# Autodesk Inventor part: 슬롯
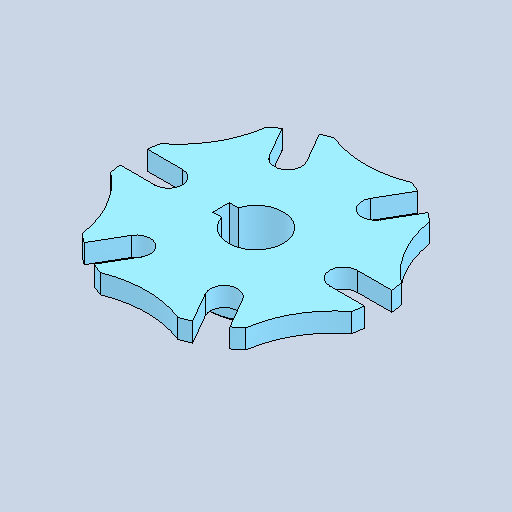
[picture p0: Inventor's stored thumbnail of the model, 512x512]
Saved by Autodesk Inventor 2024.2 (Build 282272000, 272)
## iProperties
Created: 2025-09
Part Number: 슬롯
Material: 강철, 합금
Document SubType Name: Modeling
Designer: home
Density: 7.73 g/cm^3
Appearance: 기본값
Author: jhkim
Sending System: Autodesk Inventor 2026
Preprocessor: ST-DEVELOPER v20.1
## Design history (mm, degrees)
feature "솔리드1"
node "솔리드2"
